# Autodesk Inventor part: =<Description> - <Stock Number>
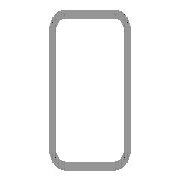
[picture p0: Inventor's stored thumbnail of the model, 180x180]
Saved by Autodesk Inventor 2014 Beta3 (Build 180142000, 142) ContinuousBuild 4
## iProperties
IsCustomPart: 1
Created: 2011-11
Part Number: =<Description> - <Stock Number>
Material: Steel, Mild
Description: Tube
Document SubType Name: Modeling
Standard: ANSI
Designer: Thom Tremblay
Standards Organization: ANSI
Language: en-US
Size Designation: 5x3x3/16
Categories: <MemberInstance><Categories><Category DisplayName="Structural Shapes" InternalName="089c4875-fa83-4c05-b084-43b9cc11f5ed" Mnemonic="GRDR"><CategoryParameter Dis
Stock Number: 5x3x3/16
Density: 7.86 g/cm^3
Appearance: Steel
_CCFamilyMember: 33
_CCFamilyDisplayName: ANSI AISC (Rectangular) - Tube
_FrameMemberDoc: Frame Member File
_Version: 15.0.0
_GetPNFromCC: 1
G_L: 18.747 in
G_W: 3.000 in
G_H: 5.000 in
+CF1ADD6C-EB40-4606-989C-EC2802D0A71C+CUTDETAIL5: Cut
+B2A553CF-D4ED-4223-AC76-4A511DF4A8BA+CUTDETAIL6: Cut
Author: Thom Tremblay
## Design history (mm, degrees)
node "Start plane"
node "End plane"
node "Driven Length"
  sketch "Sketch3"
    geometry: L1 (0, 0)-(10, 0) reference
    constraints: 2 end point, 1 horizontal
  workplane "Work Plane3"
  sketch "Sketch4"
    geometry: L1 (-2, 0)-(12, 0) reference; L2 (-53.343, 476.185)-(53.343, 476.185) reference
    dimensions: "d19" = 476.18539 distance between parallel lines of L1 L2 (derived)
sketch "Sweep Path"
  geometry: L1 through (609.6, 0) direction (-1, -0); 1 other entity
  constraints: 5 horizontal
node "Orientation Work Plane"
feature "Body" dims "d20" = 0
workplane "Work Plane15"
sketch "Sketch15"
  geometry: L1 (-38.6, 73.96)-(38.6, 73.96); L2 (-38.6, -73.96)-(38.6, -73.96)
  constraints: 4 end point
feature "LoftSrf11" sketch "Sketch15" dims "d61" = 0, "d62" = 90 deg, "d63" = 0, "d64" = 90 deg
split "Split11"
workplane "Work Plane16"
sketch "Sketch16"
  geometry: L1 (-38.6, 73.96)-(38.6, 73.96); L2 (-38.6, -73.96)-(38.6, -73.96)
  constraints: 4 end point
feature "LoftSrf12" sketch "Sketch16" dims "d65" = 0, "d66" = 90 deg, "d67" = 0, "d68" = 90 deg
split "Split12"
workplane "Work Plane17"
sketch "Sketch17"
  geometry: L1 (-38.6, 64)-(38.6, 64); L2 (-38.6, -64)-(38.6, -64)
  constraints: 4 end point
feature "LoftSrf13" sketch "Sketch17" dims "d69" = 0, "d70" = 90 deg, "d71" = 0, "d72" = 90 deg
split "Split13"
workplane "Work Plane18"
sketch "Sketch18"
  geometry: L1 (-38.6, 64)-(38.6, 64); L2 (-38.6, -64)-(38.6, -64)
  constraints: 4 end point
feature "LoftSrf14" sketch "Sketch18" dims "d73" = 0, "d74" = 90 deg, "d75" = 0, "d76" = 90 deg
split "Split14"
workplane "Work Plane19"
sketch "Sketch19"
  geometry: L1 (-38.6, 64)-(38.6, 64); L2 (-38.6, -64)-(38.6, -64)
  constraints: 4 end point
feature "LoftSrf15" sketch "Sketch19" dims "d77" = 0, "d78" = 90 deg, "d79" = 0, "d80" = 90 deg
split "Split15"
workplane "Work Plane20"
sketch "Sketch20"
  geometry: L1 (-38.6, 64)-(38.6, 64); L2 (-38.6, -64)-(38.6, -64)
  constraints: 4 end point
feature "LoftSrf16" sketch "Sketch20" dims "d81" = 0, "d82" = 90 deg, "d83" = 0, "d84" = 90 deg
split "Split16"
body "Solid1"
sketch "Sketch"
  geometry: L1 (-38.1, -53.975)-(-38.1, 53.975); L2 (-28.575, 63.5)-(28.575, 63.5); L3 (38.1, 53.975)-(38.1, -53.975); L4 (28.575, -63.5)-(-28.575, -63.5); L5 (-28.575, 58.737)-(28.575, 58.737); L6 (33.338, 53.975)-(33.338, -53.975); L7 (28.575, -58.737)-(-28.575, -58.737); L8 (-33.338, -53.975)-(-33.338, 53.975); L9 (0, 36.948)-(0, -36.948); L10 (-23.079, 0)-(23.079, 0); A1 r 9.525 centre (-28.575, -53.975) between (-38.1, -53.975) and (-28.575, -63.5); A2 r 9.525 centre (-28.575, 53.975) between (-28.575, 63.5) and (-38.1, 53.975); A3 r 9.525 centre (28.575, 53.975) between (38.1, 53.975) and (28.575, 63.5); A4 r 9.525 centre (28.575, -53.975) between (28.575, -63.5) and (38.1, -53.975); A5 r 4.763 centre (-28.575, 53.975) between (-28.575, 58.737) and (-33.338, 53.975); A6 r 4.763 centre (28.575, 53.975) between (33.338, 53.975) and (28.575, 58.737); A7 r 4.763 centre (28.575, -53.975) between (28.575, -58.737) and (33.338, -53.975); A8 r 4.763 centre (-28.575, -53.975) between (-33.338, -53.975) and (-28.575, -58.737)
  constraints: 20 end point, 16 point on circle, 8 centre point, 8 tangent, 4 parallel, 3 equal radius, 2 perpendicular, 7 other
  dimensions: "d10" = 127 distance between parallel lines of L2 L4 (= G_H); "d11" = 76.2 distance between parallel lines of L1 L3 (= G_W); "d12" = 4.7625 distance between parallel lines of L3 L6 (= G_T); "d15" = 63.5 distance between parallel lines of L2 L10 (= 0.5 x d10); "d16" = 38.1 distance between parallel lines of L9 L3 (= 0.5 x d11); "d17" = 9.525 radius of A1 (= G_IR)
body "Srf11"
body "Srf12"
body "Srf13"
body "Srf14"
body "Srf15"
body "Srf16"
other parameters: "G_W" = 76.2 [user parameter; used in 1 equation term], "G_H" = 127 [user parameter; used in 1 equation term], "G_T" = 4.7625 [user parameter; used in 1 equation term], "G_IR" = 9.525 [user parameter; used in 1 equation term], "G_L" = 476.18539 (= d19) [user parameter], "G_OFFSET_START" = 0 [user parameter; used in 1 equation term], "G_OFFSET_END" = 0 [user parameter; used in 1 equation term], "d13" = 0 (computed from G_OFFSET_START), "d14" = 476.18539 (= G_OFFSET_END + B_L), "B_L" = 476.18539 [user parameter; used in 1 equation term], "d18" = 90 deg
